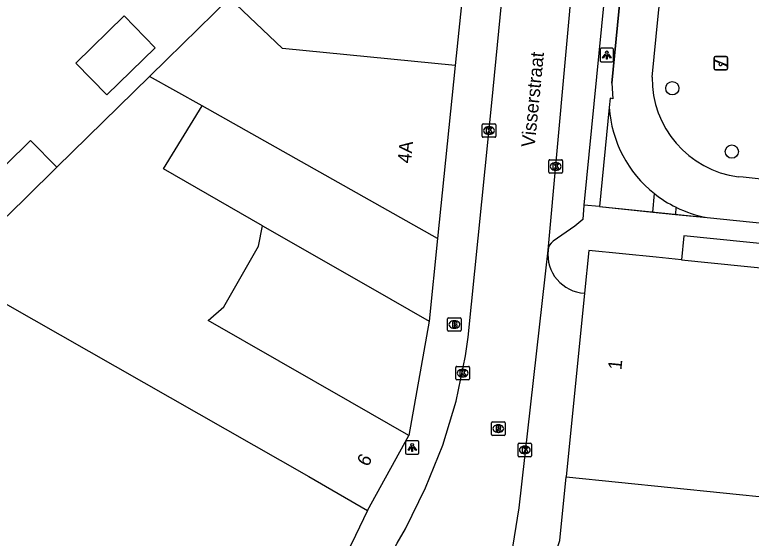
# Model space of a CAD drawing. Extents: x 160861 to 161308, y 384024 to 384878.
# Drawn here: x 161083.3 to 161137.7, y 384599.3 to 384638 of the extents above; entities that cross this region are included whole.
import ezdxf

# ---------------------------------------------------------------- set-up
doc = ezdxf.new("R2010")
doc.units = 0
for name, color, linetype in [('IMGEO_Boom', 7, 'Continuous'), ('IMGEO_Brandkraan', 7, 'Continuous'), ('IMGEO_Hek', 7, 'Continuous'), ('IMGEO_Kolk', 7, 'Continuous'), ('IMGEO_Lichtpunt', 7, 'Continuous'), ('IMGEO_Openbare_ruimte_label', 7, 'Continuous'), ('IMGEO_Pand', 7, 'Continuous'), ('IMGEO_Pand_nummerreeks', 7, 'Continuous'), ('IMGEO_Parkeervlak_open', 7, 'Continuous'), ('IMGEO_Rijbaan_lokaal_open', 7, 'Continuous'), ('IMGEO_Rioolput', 7, 'Continuous'), ('IMGEO_Speelvoorziening', 7, 'Continuous'), ('IMGEO_Voetpad_gesloten', 7, 'Continuous'), ('IMGEO_Voetpad_open', 7, 'Continuous')]:
    doc.layers.add(name, color=color, linetype=linetype)

msp = doc.modelspace()

# ---------------------------------------------------------------- linework, layer by layer
at = {"layer": 'IMGEO_Boom'}
for centre in [(161131.847, 384632.567), (161136.247, 384627.885)]:
    msp.add_circle(centre, 0.489, dxfattribs=at)
at = {"layer": 'IMGEO_Brandkraan'}
for p, q in [((161115.248, 384614.676), (161115.248, 384615.528)), ((161115.323, 384615.602), (161116.175, 384615.602)), ((161115.736, 384615.382), (161115.761, 384615.382)), ((161116.249, 384615.528), (161116.249, 384614.676)), ((161115.759, 384614.822), (161115.734, 384614.822)), ((161116.175, 384614.602), (161115.323, 384614.602))]:
    msp.add_line(p, q, dxfattribs=at)
for points in [[(161115.248, 384614.676), (161115.248, 384615.528)], [(161115.323, 384615.602), (161116.175, 384615.602)], [(161115.596, 384615.302), (161115.596, 384614.902), (161115.809, 384614.902)], [(161115.827, 384615.302), (161115.596, 384615.302)], [(161116.249, 384615.528), (161116.249, 384614.676)], [(161115.775, 384615.221), (161115.721, 384615.221), (161115.721, 384615.145)], [(161115.721, 384615.145), (161115.774, 384615.145)], [(161115.783, 384615.069), (161115.721, 384615.069), (161115.721, 384614.988)], [(161115.721, 384614.988), (161115.783, 384614.988)], [(161116.175, 384614.602), (161115.323, 384614.602)]]:
    msp.add_lwpolyline(points, dxfattribs=at)
for centre, radius, start, end in [((161115.325, 384615.526), 0.0765, 91.552, 178.448), ((161115.325, 384615.526), 0.0765, 91.552, 178.448), ((161115.831, 384615.157), 0.145, 59.4692, 91.5367), ((161116.173, 384615.526), 0.0765, 1.552, 88.448), ((161116.173, 384615.526), 0.0765, 1.552, 88.448), ((161115.776, 384615.183), 0.0379, 267.8285, 90.9355), ((161115.784, 384615.028), 0.0404, 269.8759, 90.5077), ((161115.815, 384615.153), 0.251, 268.6676, 293.5347), ((161115.856, 384615.204), 0.0922, 285.5137, 58.1501), ((161115.861, 384615.012), 0.105, 301.3115, 78.989), ((161115.325, 384614.678), 0.0765, 181.552, 268.448), ((161115.325, 384614.678), 0.0765, 181.552, 268.448), ((161116.173, 384614.678), 0.0765, 271.552, 358.448), ((161116.173, 384614.678), 0.0765, 271.552, 358.448)]:
    msp.add_arc(centre, radius, start, end, dxfattribs=at)
for centre, major_axis, ratio, start_param, end_param in [((161115.735, 384615.102), (-0.387, 0.002), 0.722429, 4.712389, 7.853982), ((161115.76, 384615.102), (-0.39, 0.002), 0.717154, 1.570796, 4.712389)]:
    msp.add_ellipse(centre, major_axis=major_axis, ratio=ratio, start_param=start_param, end_param=end_param, dxfattribs=at)
at = {"layer": 'IMGEO_Hek'}
for points in [[(161127.369, 384632.954), (161128.516, 384644.573)], [(161127.369, 384632.954), (161127.451, 384631.797)], [(161127.451, 384631.797), (161127.254, 384631.835), (161127.186, 384631.139)], [(161127.186, 384631.139), (161126.468, 384623.818)], [(161126.468, 384623.818), (161134.423, 384623.005)], [(161134.423, 384623.005), (161176.051, 384618.751)]]:
    msp.add_lwpolyline(points, dxfattribs=at)
at = {"layer": 'IMGEO_Kolk'}
for p, q in [((161117.807, 384629.015), (161117.807, 384629.867)), ((161117.882, 384629.941), (161118.734, 384629.941)), ((161118.295, 384629.721), (161118.32, 384629.721)), ((161118.808, 384629.867), (161118.808, 384629.015)), ((161118.734, 384628.941), (161117.882, 384628.941)), ((161118.318, 384629.161), (161118.293, 384629.161)), ((161122.805, 384627.287), (161123.657, 384627.287)), ((161122.73, 384626.361), (161122.73, 384627.213)), ((161123.218, 384627.067), (161123.243, 384627.067)), ((161123.731, 384627.213), (161123.731, 384626.361)), ((161123.657, 384626.287), (161122.805, 384626.287)), ((161123.241, 384626.507), (161123.216, 384626.507)), ((161115.853, 384611.081), (161115.853, 384611.933)), ((161115.928, 384612.007), (161116.78, 384612.007)), ((161116.341, 384611.787), (161116.366, 384611.787)), ((161116.854, 384611.933), (161116.854, 384611.081)), ((161116.78, 384611.007), (161115.928, 384611.007)), ((161116.364, 384611.227), (161116.339, 384611.227)), ((161120.447, 384605.399), (161120.447, 384606.251)), ((161120.522, 384606.325), (161121.374, 384606.325)), ((161120.935, 384606.105), (161120.96, 384606.105)), ((161121.448, 384606.251), (161121.448, 384605.399)), ((161120.958, 384605.545), (161120.933, 384605.545)), ((161121.374, 384605.325), (161120.522, 384605.325))]:
    msp.add_line(p, q, dxfattribs=at)
for points in [[(161117.807, 384629.015), (161117.807, 384629.867)], [(161117.882, 384629.941), (161118.734, 384629.941)], [(161118.128, 384629.641), (161118.251, 384629.641), (161118.251, 384629.49), (161118.381, 384629.641), (161118.545, 384629.641), (161118.399, 384629.49), (161118.552, 384629.241), (161118.4, 384629.241), (161118.315, 384629.405), (161118.251, 384629.338), (161118.251, 384629.241), (161118.128, 384629.241), (161118.128, 384629.641)], [(161118.808, 384629.867), (161118.808, 384629.015)], [(161118.734, 384628.941), (161117.882, 384628.941)], [(161122.805, 384627.287), (161123.657, 384627.287)], [(161122.73, 384626.361), (161122.73, 384627.213)], [(161123.051, 384626.987), (161123.174, 384626.987), (161123.174, 384626.836), (161123.304, 384626.987), (161123.468, 384626.987), (161123.322, 384626.836), (161123.475, 384626.587), (161123.323, 384626.587), (161123.238, 384626.751), (161123.174, 384626.684), (161123.174, 384626.587), (161123.051, 384626.587), (161123.051, 384626.987)], [(161123.731, 384627.213), (161123.731, 384626.361)], [(161123.657, 384626.287), (161122.805, 384626.287)], [(161115.853, 384611.081), (161115.853, 384611.933)], [(161115.928, 384612.007), (161116.78, 384612.007)], [(161116.174, 384611.707), (161116.297, 384611.707), (161116.297, 384611.556), (161116.427, 384611.707), (161116.591, 384611.707), (161116.445, 384611.556), (161116.598, 384611.307), (161116.446, 384611.307), (161116.361, 384611.471), (161116.297, 384611.404), (161116.297, 384611.307), (161116.174, 384611.307), (161116.174, 384611.707)], [(161116.854, 384611.933), (161116.854, 384611.081)], [(161116.78, 384611.007), (161115.928, 384611.007)], [(161120.447, 384605.399), (161120.447, 384606.251)], [(161120.522, 384606.325), (161121.374, 384606.325)], [(161121.448, 384606.251), (161121.448, 384605.399)], [(161120.768, 384606.025), (161120.891, 384606.025), (161120.891, 384605.874), (161121.021, 384606.025), (161121.185, 384606.025), (161121.039, 384605.874), (161121.192, 384605.625), (161121.04, 384605.625), (161120.955, 384605.789), (161120.891, 384605.722), (161120.891, 384605.625), (161120.768, 384605.625), (161120.768, 384606.025)], [(161121.374, 384605.325), (161120.522, 384605.325)]]:
    msp.add_lwpolyline(points, dxfattribs=at)
for centre, start, end in [((161117.884, 384629.865), 91.552, 178.448), ((161117.884, 384629.865), 91.552, 178.448), ((161118.732, 384629.865), 1.552, 88.448), ((161118.732, 384629.865), 1.552, 88.448), ((161117.884, 384629.017), 181.552, 268.448), ((161117.884, 384629.017), 181.552, 268.448), ((161118.732, 384629.017), 271.552, 358.448), ((161118.732, 384629.017), 271.552, 358.448), ((161122.807, 384627.211), 91.552, 178.448), ((161122.807, 384627.211), 91.552, 178.448), ((161123.655, 384627.211), 1.552, 88.448), ((161123.655, 384627.211), 1.552, 88.448), ((161122.807, 384626.363), 181.552, 268.448), ((161122.807, 384626.363), 181.552, 268.448), ((161123.655, 384626.363), 271.552, 358.448), ((161123.655, 384626.363), 271.552, 358.448), ((161115.93, 384611.931), 91.552, 178.448), ((161115.93, 384611.931), 91.552, 178.448), ((161116.778, 384611.931), 1.552, 88.448), ((161116.778, 384611.931), 1.552, 88.448), ((161115.93, 384611.083), 181.552, 268.448), ((161115.93, 384611.083), 181.552, 268.448), ((161116.778, 384611.083), 271.552, 358.448), ((161116.778, 384611.083), 271.552, 358.448), ((161120.524, 384606.249), 91.552, 178.448), ((161120.524, 384606.249), 91.552, 178.448), ((161121.372, 384606.249), 1.552, 88.448), ((161121.372, 384606.249), 1.552, 88.448), ((161120.524, 384605.401), 181.552, 268.448), ((161120.524, 384605.401), 181.552, 268.448), ((161121.372, 384605.401), 271.552, 358.448), ((161121.372, 384605.401), 271.552, 358.448)]:
    msp.add_arc(centre, 0.0765, start, end, dxfattribs=at)
for centre, major_axis, ratio, start_param, end_param in [((161118.294, 384629.441), (-0.387, 0.002), 0.722429, 4.712389, 7.853982), ((161118.319, 384629.441), (-0.39, 0.002), 0.717154, 1.570796, 4.712389), ((161123.217, 384626.787), (-0.387, 0.002), 0.722429, 4.712389, 7.853982), ((161123.242, 384626.787), (-0.39, 0.002), 0.717154, 1.570796, 4.712389), ((161116.34, 384611.507), (-0.387, 0.002), 0.722429, 4.712389, 7.853982), ((161116.365, 384611.507), (-0.39, 0.002), 0.717154, 1.570796, 4.712389), ((161120.934, 384605.825), (-0.387, 0.002), 0.722429, 4.712389, 7.853982), ((161120.959, 384605.825), (-0.39, 0.002), 0.717154, 1.570796, 4.712389)]:
    msp.add_ellipse(centre, major_axis=major_axis, ratio=ratio, start_param=start_param, end_param=end_param, dxfattribs=at)
at = {"layer": 'IMGEO_Lichtpunt'}
for p, q in [((161126.507, 384635.427), (161126.507, 384634.62)), ((161126.507, 384635.427), (161126.507, 384634.62)), ((161127.409, 384635.522), (161126.601, 384635.522)), ((161127.409, 384635.522), (161126.601, 384635.522)), ((161127.503, 384634.62), (161127.503, 384635.427)), ((161127.503, 384634.62), (161127.503, 384635.427)), ((161126.601, 384634.526), (161127.409, 384634.526)), ((161126.601, 384634.526), (161127.409, 384634.526)), ((161112.135, 384606.411), (161112.135, 384605.604)), ((161112.135, 384606.411), (161112.135, 384605.604)), ((161113.037, 384606.506), (161112.229, 384606.506)), ((161113.037, 384606.506), (161112.229, 384606.506)), ((161113.131, 384605.604), (161113.131, 384606.411)), ((161113.131, 384605.604), (161113.131, 384606.411)), ((161112.229, 384605.51), (161113.037, 384605.51)), ((161112.229, 384605.51), (161113.037, 384605.51))]:
    msp.add_line(p, q, dxfattribs=at)
for points in [[(161126.881, 384635.091), (161126.92, 384635.063), (161126.732, 384634.801), (161126.694, 384634.828), (161126.881, 384635.091)], [(161126.983, 384635.043), (161127.03, 384635.043), (161127.03, 384634.721), (161126.983, 384634.721), (161126.983, 384635.043)], [(161127.093, 384635.063), (161127.131, 384635.09), (161127.318, 384634.828), (161127.279, 384634.8), (161127.093, 384635.063)], [(161112.509, 384606.075), (161112.548, 384606.047), (161112.36, 384605.785), (161112.322, 384605.812), (161112.509, 384606.075)], [(161112.721, 384606.047), (161112.759, 384606.074), (161112.946, 384605.812), (161112.907, 384605.784), (161112.721, 384606.047)], [(161112.611, 384606.027), (161112.658, 384606.027), (161112.658, 384605.705), (161112.611, 384605.705), (161112.611, 384606.027)]]:
    msp.add_lwpolyline(points, dxfattribs=at)
for centre in [(161127.006, 384635.225), (161112.634, 384606.209)]:
    msp.add_circle(centre, 0.0994, dxfattribs=at)
for centre, start, end in [((161126.601, 384635.427), 90, 180), ((161126.601, 384635.427), 90, 180), ((161127.409, 384635.427), 0, 90), ((161127.409, 384635.427), 0, 90), ((161126.601, 384634.62), 180, 270), ((161126.601, 384634.62), 180, 270), ((161127.409, 384634.62), 270, 0), ((161127.409, 384634.62), 270, 360), ((161112.229, 384606.411), 90, 180), ((161112.229, 384606.411), 90, 180), ((161113.037, 384606.411), 0, 90), ((161113.037, 384606.411), 0, 90), ((161112.229, 384605.604), 180, 270), ((161112.229, 384605.604), 180, 270), ((161113.037, 384605.604), 270, 0), ((161113.037, 384605.604), 270, 360)]:
    msp.add_arc(centre, 0.0946, start, end, dxfattribs=at)
at = {"layer": 'IMGEO_Pand'}
for points in [[(161116.593, 384641.867), (161115.812, 384634.245)], [(161093.223, 384633.447), (161094.493, 384634.694), (161099.122, 384639.241)], [(161115.812, 384634.245), (161103.042, 384635.508), (161099.122, 384639.241)], [(161091.358, 384637.915), (161093.649, 384635.561), (161090.067, 384632.073), (161087.775, 384634.427), (161091.358, 384637.915)], [(161115.812, 384634.245), (161114.502, 384621.465)], [(161093.223, 384633.447), (161090.926, 384631.191), (161086.382, 384626.729)], [(161097.104, 384631.262), (161093.223, 384633.447)], [(161101.573, 384622.408), (161094.262, 384626.605), (161097.104, 384631.262)], [(161114.502, 384621.465), (161097.104, 384631.262)], [(161086.382, 384626.729), (161084.433, 384628.715), (161080.758, 384625.105)], [(161082.708, 384623.12), (161086.076, 384626.428), (161086.382, 384626.729)], [(161112.379, 384606.904), (161108.04, 384609.387), (161097.556, 384615.387), (161098.717, 384616.408), (161101.279, 384620.893), (161101.573, 384622.408)], [(161101.573, 384622.408), (161109.539, 384617.834), (161113.875, 384615.344)], [(161114.502, 384621.465), (161113.875, 384615.344)], [(161132.513, 384619.882), (161130.643, 384620.071), (161125.668, 384620.573), (161125.354, 384617.415)], [(161132.513, 384619.882), (161156.651, 384617.445), (161156.245, 384613.452)], [(161078.48, 384618.967), (161104.998, 384603.863), (161109.327, 384601.361)], [(161125.354, 384617.415), (161124.003, 384603.832)], [(161109.327, 384601.361), (161112.379, 384606.904)], [(161121.366, 384592.819), (161123.534, 384599.122), (161124.003, 384603.832)], [(161124.003, 384603.832), (161154.927, 384600.692)], [(161109.327, 384601.361), (161108.157, 384598.883), (161101.019, 384586.171)]]:
    msp.add_lwpolyline(points, dxfattribs=at)
at = {"layer": 'IMGEO_Parkeervlak_open'}
msp.add_lwpolyline([(161113.875, 384615.344), (161112.379, 384606.904)], dxfattribs=at)
at = {"layer": 'IMGEO_Rijbaan_lokaal_open'}
for points in [[(161122.667, 384620.591), (161125.239, 384648.923), (161128.005, 384675.821)], [(161089.873, 384560.302), (161096.821, 384572.592), (161111.529, 384598.935), (161112.129, 384599.985), (161113.605, 384603.016), (161114.883, 384606.177), (161115.873, 384609.439), (161116.568, 384612.776), (161116.766, 384614.158), (161118.517, 384631.497), (161119.973, 384646.411)], [(161118.543, 384511.891), (161101.766, 384537.337), (161101.606, 384537.591), (161101.292, 384538.17), (161101.031, 384538.775), (161100.825, 384539.4), (161100.676, 384540.042), (161100.584, 384540.694), (161100.552, 384541.352), (161100.578, 384542.01), (161100.662, 384542.663), (161100.805, 384543.305), (161101.005, 384543.933), (161106.734, 384559.483), (161117.49, 384589.167), (161118.541, 384592.018), (161119.849, 384597.258), (161120.522, 384601.554), (161122.667, 384620.591)]]:
    msp.add_lwpolyline(points, dxfattribs=at)
at = {"layer": 'IMGEO_Rioolput'}
for p, q in [((161118.487, 384606.976), (161118.487, 384607.828)), ((161118.562, 384607.902), (161119.414, 384607.902)), ((161118.975, 384607.682), (161119, 384607.682)), ((161119.488, 384607.828), (161119.488, 384606.976)), ((161118.998, 384607.122), (161118.973, 384607.122)), ((161119.414, 384606.902), (161118.562, 384606.902))]:
    msp.add_line(p, q, dxfattribs=at)
for points in [[(161118.487, 384606.976), (161118.487, 384607.828)], [(161118.562, 384607.902), (161119.414, 384607.902)], [(161119.488, 384607.828), (161119.488, 384606.976)], [(161119.076, 384607.6), (161118.824, 384607.602), (161118.824, 384607.202)], [(161118.824, 384607.202), (161118.948, 384607.202), (161118.948, 384607.364), (161118.959, 384607.364)], [(161119.002, 384607.521), (161118.948, 384607.521), (161118.948, 384607.44)], [(161118.948, 384607.44), (161119, 384607.44)], [(161119.006, 384607.335), (161119.077, 384607.202), (161119.217, 384607.202), (161119.152, 384607.328)], [(161119.414, 384606.902), (161118.562, 384606.902)]]:
    msp.add_lwpolyline(points, dxfattribs=at)
for centre, radius, start, end in [((161118.564, 384607.826), 0.0765, 91.552, 178.448), ((161118.564, 384607.826), 0.0765, 91.552, 178.448), ((161119.412, 384607.826), 0.0765, 1.552, 88.448), ((161119.412, 384607.826), 0.0765, 1.552, 88.448), ((161118.958, 384607.311), 0.0533, 26.0293, 88.6989), ((161118.984, 384607.629), 0.19, 274.7715, 282.9687), ((161119.008, 384607.425), 0.0964, 77.0061, 93.1865), ((161119.022, 384607.482), 0.0378, 276.6634, 79.6772), ((161119.075, 384607.49), 0.109, 350.3612, 89.416), ((161119.073, 384607.49), 0.112, 277.5842, 350.9817), ((161119.057, 384607.275), 0.108, 29.5134, 73.7905), ((161118.564, 384606.978), 0.0765, 181.552, 268.448), ((161118.564, 384606.978), 0.0765, 181.552, 268.448), ((161119.412, 384606.978), 0.0765, 271.552, 358.448), ((161119.412, 384606.978), 0.0765, 271.552, 358.448)]:
    msp.add_arc(centre, radius, start, end, dxfattribs=at)
for centre, major_axis, ratio, start_param, end_param in [((161118.974, 384607.402), (-0.387, 0.002), 0.722429, 4.712389, 7.853982), ((161118.999, 384607.402), (-0.39, 0.002), 0.717154, 1.570796, 4.712389)]:
    msp.add_ellipse(centre, major_axis=major_axis, ratio=ratio, start_param=start_param, end_param=end_param, dxfattribs=at)
at = {"layer": 'IMGEO_Speelvoorziening'}
for p, q in [((161135.039, 384634.918), (161135.829, 384634.918)), ((161135.829, 384634.918), (161135.039, 384634.918)), ((161134.939, 384634.018), (161134.939, 384634.818)), ((161134.939, 384634.818), (161134.939, 384634.018)), ((161135.322, 384634.446), (161134.983, 384634.583)), ((161135.008, 384634.643), (161135.884, 384634.29)), ((161135.86, 384634.23), (161135.52, 384634.367)), ((161135.929, 384634.818), (161135.929, 384634.018)), ((161135.929, 384634.018), (161135.929, 384634.818)), ((161135.829, 384633.918), (161135.039, 384633.918)), ((161135.039, 384633.918), (161135.829, 384633.918))]:
    msp.add_line(p, q, dxfattribs=at)
for centre, radius, start, end in [((161135.039, 384634.818), 0.1, 90, 180), ((161135.039, 384634.818), 0.1, 90, 180), ((161135.829, 384634.818), 0.1, 0, 90), ((161135.829, 384634.818), 0.1, 360, 90), ((161134.996, 384634.613), 0.0327, 68.078, 248.078), ((161135.401, 384634.356), 0.12, 130.9928, 5.1632), ((161135.039, 384634.018), 0.1, 180, 270), ((161135.039, 384634.018), 0.1, 180, 270), ((161135.829, 384634.018), 0.1, 270, 0), ((161135.829, 384634.018), 0.1, 270, 0), ((161135.872, 384634.26), 0.0327, 248.078, 68.078)]:
    msp.add_arc(centre, radius, start, end, dxfattribs=at)
at = {"layer": 'IMGEO_Voetpad_gesloten'}
for points in [[(161130.359, 384633.395), (161130.81, 384637.903), (161130.975, 384639.545), (161133.486, 384664.435)], [(161128.516, 384644.573), (161127.369, 384632.954), (161127.451, 384631.797), (161127.254, 384631.835), (161127.186, 384631.139)], [(161173.62, 384622.08), (161167.207, 384622.765), (161148.053, 384624.812), (161144.423, 384625.2), (161141.987, 384625.461), (161137.085, 384625.985), (161136.726, 384626.023)], [(161134.423, 384623.005), (161176.051, 384618.751)]]:
    msp.add_lwpolyline(points, dxfattribs=at)
for centre, radius, start, end in [((161137.677, 384633.28), 7.319, 179.0994, 262.5332), ((161136.035, 384631.727), 8.869, 183.8006, 231.6043), ((161135.996, 384631.664), 8.795, 231.5512, 243.838), ((161136.031, 384631.706), 8.848, 243.7518, 259.5275)]:
    msp.add_arc(centre, radius, start, end, dxfattribs=at)
at = {"layer": 'IMGEO_Voetpad_open'}
for points in [[(161127.346, 384644.666), (161125.308, 384623.924)], [(161127.186, 384631.139), (161126.468, 384623.818)], [(161130.41, 384623.415), (161130.527, 384624.776)], [(161125.308, 384623.924), (161125.238, 384622.874), (161124.649, 384622.382), (161123.045, 384621.254)], [(161126.468, 384623.818), (161125.308, 384623.924)], [(161126.468, 384623.818), (161130.41, 384623.415)], [(161132.118, 384623.77), (161132.085, 384623.244)], [(161130.41, 384623.415), (161132.085, 384623.244)], [(161132.085, 384623.244), (161134.423, 384623.005)], [(161158.024, 384619.088), (161132.7, 384621.651), (161132.513, 384619.882)]]:
    msp.add_lwpolyline(points, dxfattribs=at)
for centre, radius, start, end in [((161123.594, 384620.502), 0.932, 126.1304, 174.4916), ((161125.526, 384620.285), 2.875, 173.8968, 266.5678)]:
    msp.add_arc(centre, radius, start, end, dxfattribs=at)

# ---------------------------------------------------------------- texts
at = {"layer": 'IMGEO_Openbare_ruimte_label'}
msp.add_text('Visserstraat', height=1, rotation=84.3179, dxfattribs=at).set_placement((161121.672, 384628.165))
at = {"layer": 'IMGEO_Pand_nummerreeks'}
for s, rotation, p in [('4A', 84.1474, (161112.535, 384626.986)), ('1', 84.3202, (161128.083, 384611.717)), ('6', 61.1632, (161109.358, 384604.529))]:
    msp.add_text(s, height=1, rotation=rotation, dxfattribs=at).set_placement(p)

doc.saveas('drawing.dxf')
